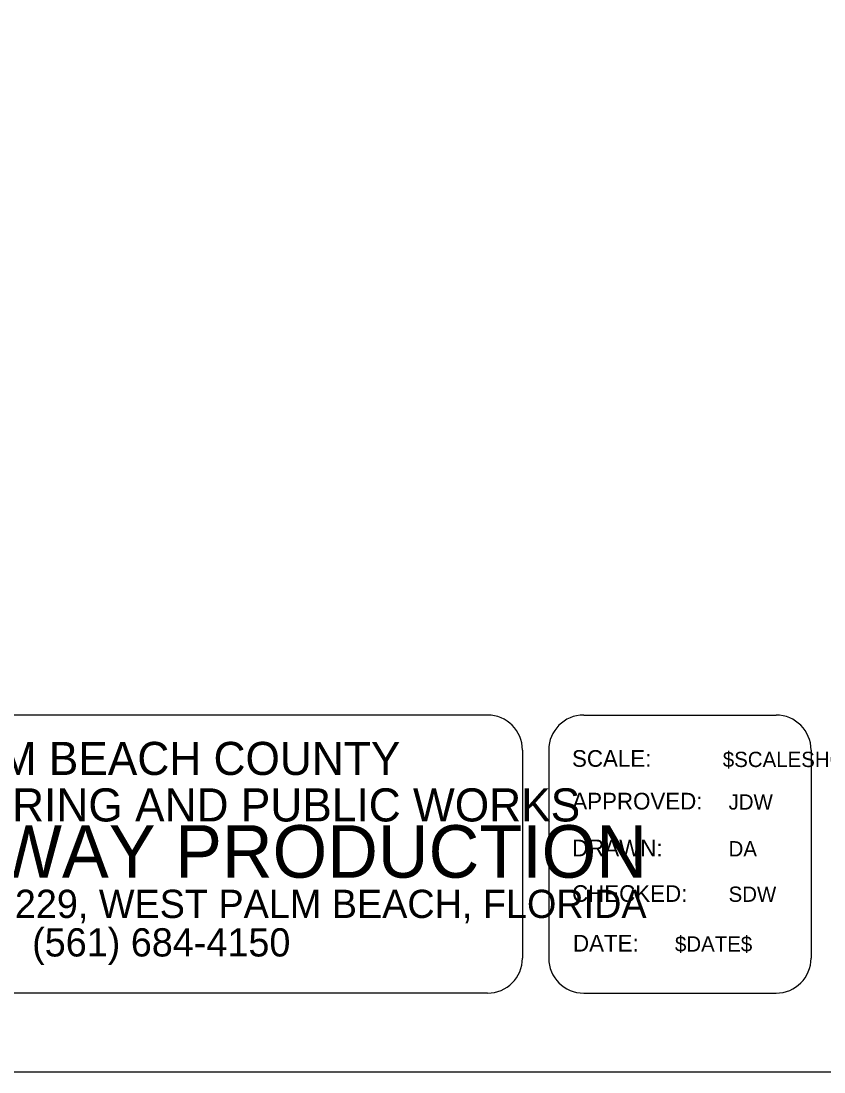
# Model space of a CAD drawing. Extents: x -0.6 to 16, y -0.9 to 9.7.
# Drawn here: x 9.999 to 12.024, y -0.9 to 1.75 of the extents above; entities that cross this region are included whole.
import ezdxf

# ---------------------------------------------------------------- set-up
doc = ezdxf.new("R2010")
doc.units = 0
for name, color, linetype in [('Default', 7, 'Continuous'), ('PlotBorder_dp', 7, 'Continuous'), ('TextMinor', 7, 'Continuous')]:
    doc.layers.add(name, color=color, linetype=linetype)

msp = doc.modelspace()

# ---------------------------------------------------------------- linework, layer by layer
at = {"layer": 'Default'}
for p, q in [((11.1756, 0), (8.7497, 0)), ((11.4182, 0), (11.9034, 0)), ((11.2638, -0.0882), (11.2638, -0.6131)), ((11.33, -0.0882), (11.33, -0.6131)), ((11.9916, -0.0882), (11.9916, -0.6131)), ((11.1756, -0.7014), (8.7497, -0.7014)), ((11.4182, -0.7014), (11.9034, -0.7014))]:
    msp.add_line(p, q, dxfattribs=at)
for centre, major_axis, start_param, end_param in [((11.1756, -0.0882), (0, 0.0882), 4.712389, 6.283185), ((11.4182, -0.0882), (0, 0.0882), 0, 1.570796), ((11.9034, -0.0882), (0, 0.0882), 4.712389, 6.283185), ((11.1756, -0.6131), (0, 0.0882), 3.141593, 4.712389), ((11.4182, -0.6131), (0, -0.0882), 4.712389, 6.283185), ((11.9034, -0.6131), (0, -0.0882), 0, 1.570796)]:
    msp.add_ellipse(centre, major_axis=major_axis, ratio=0.999927, start_param=start_param, end_param=end_param, dxfattribs=at)
at = {"layer": 'PlotBorder_dp'}
msp.add_lwpolyline([(-0.55, -0.9), (15.95, -0.9), (15.95, 9.7), (-0.55, 9.7)], close=True, dxfattribs=at)

# ---------------------------------------------------------------- texts
at = {"layer": 'Default'}
for s, height, p in [('PALM BEACH COUNTY', 0.083446, (9.7345, -0.1511)), ('ENGINEERING AND PUBLIC WORKS', 0.083468, (9.4745, -0.2683)), ('ROADWAY PRODUCTION', 0.132369, (9.4241, -0.4101)), ('P.O. BOX 21229, WEST PALM BEACH, FLORIDA', 0.071224, (9.4333, -0.5117)), ('(561) 684-4150', 0.071224, (10.0274, -0.6088))]:
    msp.add_text(s, height=height, rotation=360, dxfattribs=at).set_placement(p)
for s, height, p in [('SCALE:', 0.04207, (11.3888, -0.1305)), ('APPROVED:', 0.04207, (11.3896, -0.2381)), ('JDW', 0.03855, (11.7836, -0.2384)), ('DRAWN:', 0.04207, (11.389, -0.3563)), ('DA ', 0.03855, (11.7836, -0.3565)), ('CHECKED:', 0.04207, (11.3889, -0.4711)), ('SDW', 0.03855, (11.7836, -0.471)), ('DATE:', 0.04207, (11.3913, -0.5963)), ('$DATE$', 0.03855, (11.6484, -0.5965))]:
    msp.add_text(s, height=height, dxfattribs=at).set_placement(p)
at = {"layer": 'TextMinor'}
msp.add_text('$SCALESHORT$', height=0.038546, dxfattribs=at).set_placement((11.7691, -0.1311))

doc.saveas('drawing.dxf')
